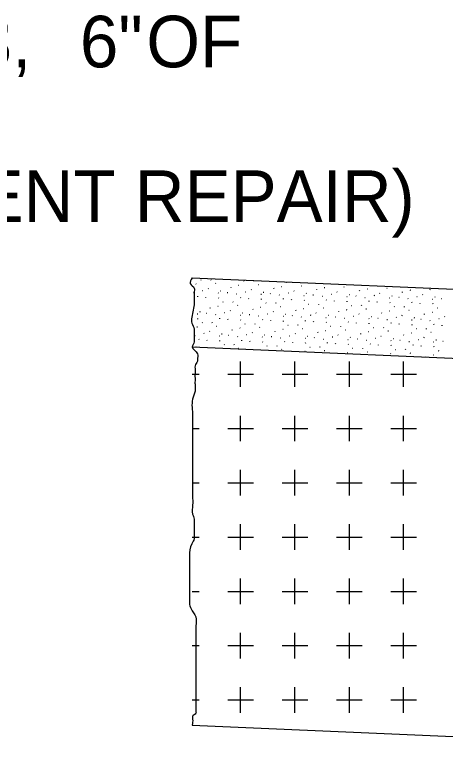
# Model space of a CAD drawing. Extents: x 0 to 34, y 0 to 22.
# Drawn here: x 20.152 to 21.318, y 3.808 to 5.839 of the extents above; entities that cross this region are included whole.
import ezdxf

# ---------------------------------------------------------------- set-up
doc = ezdxf.new("R2010")
doc.units = 0
doc.layers.add('TX_P_1', color=7, linetype='Continuous')

msp = doc.modelspace()

# ---------------------------------------------------------------- linework, layer by layer
at = {"layer": 'TX_P_1'}
for p, q in [((20.6558, 5.1199), (20.6569, 5.1197)), ((20.6839, 5.1187), (20.6833, 5.1201)), ((20.6421, 5.1086), (20.6431, 5.1082)), ((20.6953, 5.1104), (20.6964, 5.1102)), ((20.7383, 5.0987), (20.7378, 5.1002)), ((20.7583, 5.1052), (20.7593, 5.1051)), ((20.7721, 5.1167), (20.7731, 5.1166)), ((20.8003, 5.1154), (20.7996, 5.1169)), ((20.8116, 5.1071), (20.8126, 5.1069)), ((20.8746, 5.1021), (20.8756, 5.1017)), ((20.8883, 5.1134), (20.8893, 5.1132)), ((20.9164, 5.1122), (20.9161, 5.1131)), ((20.9278, 5.1039), (20.9289, 5.1037)), ((20.9908, 5.0987), (20.9919, 5.0986)), ((21.0441, 5.1006), (21.0451, 5.1004)), ((20.6361, 5.0852), (20.6371, 5.0849)), ((20.6606, 5.0907), (20.6616, 5.0906)), ((20.6758, 5.0966), (20.6769, 5.0957)), ((20.7029, 5.0841), (20.7039, 5.0839)), ((20.7091, 5.0899), (20.7103, 5.0896)), ((20.7276, 5.0857), (20.7288, 5.0854)), ((20.7523, 5.0819), (20.7534, 5.0817)), ((20.7768, 5.0876), (20.7779, 5.0874)), ((20.7921, 5.0934), (20.7931, 5.0926)), ((20.8191, 5.0807), (20.8203, 5.0806)), ((20.8254, 5.0866), (20.8264, 5.0864)), ((20.8439, 5.0824), (20.8449, 5.0822)), ((20.8544, 5.0956), (20.8539, 5.0969)), ((20.8686, 5.0786), (20.8696, 5.0784)), ((20.8931, 5.0842), (20.8941, 5.0841)), ((20.9084, 5.0901), (20.9094, 5.0892)), ((20.9416, 5.0834), (20.9428, 5.0831)), ((20.9601, 5.0791), (20.9611, 5.0789)), ((20.9708, 5.0922), (20.9703, 5.0937)), ((21.0093, 5.0811), (21.0104, 5.0809)), ((21.0246, 5.0869), (21.0256, 5.0861)), ((21.0579, 5.0801), (21.0591, 5.0799)), ((21.0871, 5.0891), (21.0866, 5.0904)), ((21.1071, 5.0956), (21.1081, 5.0952)), ((21.1256, 5.0777), (21.1268, 5.0776)), ((21.1409, 5.0836), (21.1419, 5.0827)), ((21.1604, 5.0974), (21.1614, 5.0972)), ((21.2033, 5.0857), (21.2028, 5.0871)), ((21.2233, 5.0922), (21.2244, 5.0921)), ((21.2571, 5.0804), (21.2581, 5.0794)), ((21.2766, 5.0941), (21.2776, 5.0939)), ((20.6479, 5.0739), (20.6473, 5.0754)), ((20.6699, 5.0714), (20.6694, 5.0727)), ((20.7044, 5.0699), (20.7039, 5.0712)), ((20.7154, 5.0602), (20.7166, 5.0599)), ((20.7436, 5.0589), (20.7431, 5.0604)), ((20.7643, 5.0707), (20.7636, 5.0721)), ((20.7861, 5.0681), (20.7856, 5.0694)), ((20.8208, 5.0666), (20.8203, 5.0681)), ((20.8804, 5.0674), (20.8799, 5.0689)), ((20.9024, 5.0649), (20.9018, 5.0662)), ((20.9354, 5.0774), (20.9364, 5.0772)), ((20.9369, 5.0634), (20.9364, 5.0647)), ((20.9849, 5.0754), (20.9859, 5.0751)), ((20.9966, 5.0642), (20.9961, 5.0656)), ((21.0188, 5.0616), (21.0181, 5.0629)), ((21.0516, 5.0742), (21.0528, 5.0741)), ((21.0533, 5.0601), (21.0528, 5.0616)), ((21.0764, 5.0759), (21.0774, 5.0756)), ((21.1011, 5.0721), (21.1021, 5.0719)), ((21.1129, 5.0609), (21.1124, 5.0624)), ((21.1349, 5.0584), (21.1344, 5.0597)), ((21.1679, 5.0709), (21.1689, 5.0707)), ((21.1696, 5.0569), (21.1689, 5.0582)), ((21.1743, 5.0767), (21.1753, 5.0766)), ((21.1926, 5.0726), (21.1936, 5.0724)), ((21.2173, 5.0689), (21.2184, 5.0686)), ((21.2291, 5.0577), (21.2286, 5.0591)), ((21.2419, 5.0744), (21.2429, 5.0742)), ((21.2841, 5.0677), (21.2853, 5.0676)), ((21.2904, 5.0736), (21.2914, 5.0732)), ((21.3089, 5.0694), (21.3099, 5.0691)), ((20.6388, 5.0539), (20.6398, 5.0537)), ((20.6818, 5.0422), (20.6813, 5.0437)), ((20.7018, 5.0487), (20.7029, 5.0486)), ((20.7551, 5.0507), (20.7561, 5.0504)), ((20.7979, 5.0391), (20.7974, 5.0404)), ((20.8181, 5.0456), (20.8191, 5.0454)), ((20.8318, 5.0569), (20.8328, 5.0567)), ((20.8599, 5.0557), (20.8594, 5.0571)), ((20.8713, 5.0474), (20.8724, 5.0472)), ((20.9143, 5.0357), (20.9138, 5.0371)), ((20.9343, 5.0422), (20.9354, 5.0421)), ((20.9481, 5.0537), (20.9491, 5.0534)), ((20.9761, 5.0524), (20.9756, 5.0539)), ((20.9876, 5.0442), (20.9886, 5.0439)), ((21.0506, 5.0389), (21.0518, 5.0387)), ((21.0643, 5.0504), (21.0654, 5.0502)), ((21.0924, 5.0492), (21.0919, 5.0506)), ((21.1038, 5.0409), (21.1049, 5.0406)), ((21.1806, 5.0472), (21.1816, 5.0469)), ((21.2088, 5.0459), (21.2081, 5.0474)), ((21.2201, 5.0376), (21.2211, 5.0374)), ((21.2511, 5.0551), (21.2506, 5.0564)), ((21.2858, 5.0536), (21.2853, 5.0551)), ((21.2968, 5.0439), (21.2978, 5.0437)), ((20.6463, 5.0276), (20.6474, 5.0274)), ((20.6526, 5.0334), (20.6538, 5.0331)), ((20.6711, 5.0291), (20.6721, 5.0289)), ((20.6959, 5.0254), (20.6969, 5.0252)), ((20.7203, 5.0311), (20.7214, 5.0307)), ((20.7356, 5.0367), (20.7366, 5.0359)), ((20.7626, 5.0242), (20.7638, 5.0241)), ((20.7689, 5.0301), (20.7699, 5.0299)), ((20.7873, 5.0259), (20.7884, 5.0257)), ((20.8121, 5.0221), (20.8131, 5.0219)), ((20.8366, 5.0277), (20.8378, 5.0276)), ((20.8518, 5.0336), (20.8529, 5.0327)), ((20.8789, 5.0211), (20.8799, 5.0209)), ((20.8853, 5.0269), (20.8863, 5.0266)), ((20.9036, 5.0226), (20.9046, 5.0224)), ((20.9283, 5.0189), (20.9294, 5.0187)), ((20.9529, 5.0246), (20.9539, 5.0242)), ((20.9681, 5.0302), (20.9691, 5.0294)), ((20.9951, 5.0177), (20.9963, 5.0176)), ((21.0014, 5.0236), (21.0024, 5.0234)), ((21.0199, 5.0194), (21.0209, 5.0192)), ((21.0306, 5.0326), (21.0299, 5.0339)), ((21.0691, 5.0212), (21.0701, 5.0211)), ((21.0843, 5.0271), (21.0854, 5.0262)), ((21.1176, 5.0204), (21.1188, 5.0201)), ((21.1468, 5.0292), (21.1463, 5.0306)), ((21.1669, 5.0357), (21.1679, 5.0356)), ((21.1854, 5.0181), (21.1864, 5.0177)), ((21.2006, 5.0237), (21.2018, 5.0229)), ((21.2339, 5.0171), (21.2351, 5.0169)), ((21.2629, 5.0261), (21.2624, 5.0274)), ((21.2831, 5.0324), (21.2841, 5.0322)), ((21.3169, 5.0206), (21.3179, 5.0197)), ((20.6479, 5.0134), (20.6474, 5.0147)), ((20.6591, 5.0036), (20.6601, 5.0034)), ((20.6871, 5.0024), (20.6866, 5.0037)), ((20.7076, 5.0142), (20.7071, 5.0156)), ((20.7298, 5.0116), (20.7291, 5.0131)), ((20.7643, 5.0102), (20.7638, 5.0116)), ((20.7753, 5.0004), (20.7764, 5.0002)), ((20.8034, 4.9992), (20.8029, 5.0006)), ((20.8239, 5.0111), (20.8234, 5.0124)), ((20.8459, 5.0084), (20.8454, 5.0097)), ((20.8804, 5.0069), (20.8799, 5.0082)), ((20.8916, 4.9971), (20.8926, 4.9969)), ((20.9198, 4.9959), (20.9191, 4.9972)), ((20.9401, 5.0077), (20.9396, 5.0091)), ((20.9621, 5.0051), (20.9616, 5.0064)), ((20.9968, 5.0036), (20.9963, 5.0049)), ((21.0446, 5.0156), (21.0456, 5.0154)), ((21.0564, 5.0044), (21.0559, 5.0057)), ((21.0784, 5.0017), (21.0779, 5.0032)), ((21.1114, 5.0146), (21.1124, 5.0142)), ((21.1129, 5.0004), (21.1124, 5.0017)), ((21.1361, 5.0161), (21.1373, 5.0159)), ((21.1609, 5.0124), (21.1619, 5.0122)), ((21.1728, 5.0012), (21.1721, 5.0026)), ((21.1948, 4.9986), (21.1941, 4.9999)), ((21.2276, 5.0112), (21.2288, 5.0111)), ((21.2293, 4.9971), (21.2288, 4.9984)), ((21.2524, 5.0129), (21.2534, 5.0127)), ((21.2771, 5.0091), (21.2783, 5.0089)), ((21.2889, 4.9979), (21.2884, 4.9992)), ((21.3016, 5.0147), (21.3026, 5.0146)), ((21.3109, 4.9952), (21.3104, 4.9967)), ((20.6453, 4.9922), (20.6464, 4.9921)), ((20.6791, 4.9804), (20.6801, 4.9796)), ((20.6986, 4.9942), (20.6996, 4.9939)), ((20.7414, 4.9826), (20.7409, 4.9839)), ((20.7616, 4.9891), (20.7628, 4.9887)), ((20.7953, 4.9771), (20.7964, 4.9762)), ((20.8148, 4.9909), (20.8159, 4.9907)), ((20.8578, 4.9792), (20.8573, 4.9807)), ((20.8779, 4.9857), (20.8789, 4.9856)), ((20.9311, 4.9876), (20.9321, 4.9874)), ((20.9739, 4.9761), (20.9734, 4.9774)), ((20.9941, 4.9826), (20.9951, 4.9822)), ((21.0078, 4.9939), (21.0088, 4.9937)), ((21.0359, 4.9927), (21.0354, 4.9941)), ((21.0473, 4.9844), (21.0483, 4.9842)), ((21.1103, 4.9792), (21.1114, 4.9791)), ((21.1241, 4.9906), (21.1251, 4.9904)), ((21.1521, 4.9894), (21.1516, 4.9907)), ((21.1636, 4.9811), (21.1646, 4.9809)), ((21.2266, 4.9761), (21.2276, 4.9757)), ((21.2403, 4.9874), (21.2414, 4.9872)), ((21.2684, 4.9862), (21.2679, 4.9876)), ((21.2798, 4.9779), (21.2809, 4.9777)), ((20.6393, 4.9689), (20.6404, 4.9686)), ((20.6511, 4.9577), (20.6506, 4.9591)), ((20.6639, 4.9746), (20.6649, 4.9744)), ((20.6731, 4.9551), (20.6726, 4.9564)), ((20.7061, 4.9677), (20.7073, 4.9676)), ((20.7124, 4.9736), (20.7134, 4.9734)), ((20.7309, 4.9694), (20.7319, 4.9691)), ((20.7556, 4.9656), (20.7566, 4.9654)), ((20.7674, 4.9544), (20.7669, 4.9559)), ((20.7801, 4.9712), (20.7811, 4.9711)), ((20.8224, 4.9646), (20.8234, 4.9642)), ((20.8286, 4.9702), (20.8298, 4.9701)), ((20.8471, 4.9661), (20.8483, 4.9659)), ((20.8719, 4.9624), (20.8729, 4.9621)), ((20.8963, 4.9681), (20.8974, 4.9677)), ((20.9116, 4.9739), (20.9128, 4.9731)), ((20.9386, 4.9612), (20.9396, 4.9611)), ((20.9449, 4.9671), (20.9461, 4.9669)), ((20.9634, 4.9629), (20.9644, 4.9626)), ((20.9881, 4.9591), (20.9891, 4.9589)), ((21.0126, 4.9647), (21.0136, 4.9646)), ((21.0279, 4.9706), (21.0289, 4.9697)), ((21.0549, 4.9581), (21.0559, 4.9577)), ((21.0613, 4.9637), (21.0623, 4.9636)), ((21.0796, 4.9596), (21.0806, 4.9594)), ((21.0903, 4.9727), (21.0898, 4.9742)), ((21.1044, 4.9559), (21.1054, 4.9556)), ((21.1289, 4.9616), (21.1299, 4.9612)), ((21.1441, 4.9672), (21.1451, 4.9664)), ((21.1774, 4.9606), (21.1784, 4.9604)), ((21.1959, 4.9564), (21.1969, 4.9561)), ((21.2066, 4.9694), (21.2061, 4.9709)), ((21.2451, 4.9582), (21.2463, 4.9581)), ((21.2603, 4.9641), (21.2614, 4.9632)), ((21.2938, 4.9572), (21.2948, 4.9571)), ((20.6421, 4.9377), (20.6431, 4.9376)), ((20.7078, 4.9536), (20.7073, 4.9551)), ((20.7188, 4.9439), (20.7198, 4.9437)), ((20.7469, 4.9427), (20.7464, 4.9441)), ((20.7894, 4.9519), (20.7889, 4.9532)), ((20.8239, 4.9504), (20.8234, 4.9517)), ((20.8351, 4.9407), (20.8361, 4.9404)), ((20.8631, 4.9394), (20.8626, 4.9409)), ((20.8838, 4.9512), (20.8831, 4.9526)), ((20.9056, 4.9486), (20.9051, 4.9499)), ((20.9403, 4.9471), (20.9398, 4.9486)), ((20.9513, 4.9374), (20.9524, 4.9372)), ((20.9794, 4.9362), (20.9789, 4.9376)), ((20.9999, 4.9479), (20.9994, 4.9494)), ((21.0219, 4.9454), (21.0214, 4.9467)), ((21.0566, 4.9439), (21.0559, 4.9452)), ((21.1161, 4.9447), (21.1156, 4.9461)), ((21.1383, 4.9421), (21.1376, 4.9434)), ((21.1711, 4.9547), (21.1723, 4.9546)), ((21.1728, 4.9406), (21.1723, 4.9421)), ((21.2206, 4.9526), (21.2216, 4.9524)), ((21.2324, 4.9414), (21.2319, 4.9429)), ((21.2544, 4.9389), (21.2539, 4.9402)), ((21.2874, 4.9516), (21.2884, 4.9512)), ((21.2889, 4.9374), (21.2884, 4.9387)), ((21.3121, 4.9531), (21.3133, 4.9529)), ((20.7583, 4.9344), (20.7593, 4.9342)), ((20.8746, 4.9311), (20.8756, 4.9309)), ((20.9376, 4.9259), (20.9386, 4.9257)), ((20.9908, 4.9279), (20.9919, 4.9276)), ((21.0539, 4.9227), (21.0549, 4.9226)), ((21.0676, 4.9341), (21.0686, 4.9339)), ((21.0958, 4.9329), (21.0953, 4.9342)), ((21.1071, 4.9246), (21.1081, 4.9244)), ((21.1701, 4.9194), (21.1713, 4.9192)), ((21.1838, 4.9309), (21.1849, 4.9306)), ((21.2119, 4.9296), (21.2114, 4.9311)), ((21.2233, 4.9214), (21.2244, 4.9211)), ((21.2864, 4.9162), (21.2874, 4.9161)), ((21.3001, 4.9276), (21.3011, 4.9274)), ((20.7639, 4.8289), (20.7639, 4.8984)), ((20.9113, 4.8637), (20.9113, 4.8984)), ((21.0588, 4.8289), (21.0588, 4.8984)), ((21.2061, 4.8637), (21.2061, 4.8984)), ((21.2661, 4.9101), (21.2658, 4.9111)), ((20.6324, 4.8637), (20.6511, 4.8637)), ((20.7291, 4.8637), (20.7986, 4.8637)), ((20.8766, 4.8637), (20.9113, 4.8637)), ((20.9113, 4.8289), (20.9113, 4.8637)), ((20.9113, 4.8637), (20.9461, 4.8637)), ((21.0239, 4.8637), (21.0934, 4.8637)), ((21.1714, 4.8637), (21.2061, 4.8637)), ((21.2061, 4.8289), (21.2061, 4.8637)), ((21.2061, 4.8637), (21.2409, 4.8637)), ((20.7639, 4.7162), (20.7639, 4.7509)), ((20.9113, 4.6814), (20.9113, 4.7509)), ((21.0588, 4.7162), (21.0588, 4.7509)), ((21.2061, 4.6814), (21.2061, 4.7509)), ((20.6324, 4.7162), (20.6511, 4.7162)), ((20.7291, 4.7162), (20.7639, 4.7162)), ((20.7639, 4.6814), (20.7639, 4.7162)), ((20.7639, 4.7162), (20.7986, 4.7162)), ((20.8766, 4.7162), (20.9461, 4.7162)), ((21.0239, 4.7162), (21.0588, 4.7162)), ((21.0588, 4.6814), (21.0588, 4.7162)), ((21.0588, 4.7162), (21.0934, 4.7162)), ((21.1714, 4.7162), (21.2409, 4.7162)), ((20.7639, 4.5341), (20.7639, 4.6036)), ((20.9113, 4.5687), (20.9113, 4.6036)), ((21.0588, 4.5341), (21.0588, 4.6036)), ((21.2061, 4.5687), (21.2061, 4.6036)), ((20.6324, 4.5687), (20.6511, 4.5687)), ((20.7291, 4.5687), (20.7986, 4.5687)), ((20.8766, 4.5687), (20.9113, 4.5687)), ((20.9113, 4.5341), (20.9113, 4.5687)), ((20.9113, 4.5687), (20.9461, 4.5687)), ((21.0239, 4.5687), (21.0934, 4.5687)), ((21.1714, 4.5687), (21.2061, 4.5687)), ((21.2061, 4.5341), (21.2061, 4.5687)), ((21.2061, 4.5687), (21.2409, 4.5687)), ((20.7639, 4.4214), (20.7639, 4.4561)), ((20.9113, 4.3866), (20.9113, 4.4561)), ((21.0588, 4.4214), (21.0588, 4.4561)), ((21.2061, 4.3866), (21.2061, 4.4561)), ((20.6324, 4.4214), (20.6511, 4.4214)), ((20.7291, 4.4214), (20.7639, 4.4214)), ((20.7639, 4.3866), (20.7639, 4.4214)), ((20.7639, 4.4214), (20.7986, 4.4214)), ((20.8766, 4.4214), (20.9461, 4.4214)), ((21.0239, 4.4214), (21.0588, 4.4214)), ((21.0588, 4.3866), (21.0588, 4.4214)), ((21.0588, 4.4214), (21.0934, 4.4214)), ((21.1714, 4.4214), (21.2409, 4.4214)), ((20.7639, 4.2392), (20.7639, 4.3087)), ((20.9113, 4.2739), (20.9113, 4.3087)), ((21.0588, 4.2392), (21.0588, 4.3087)), ((21.2061, 4.2739), (21.2061, 4.3087)), ((20.6324, 4.2739), (20.6511, 4.2739)), ((20.7291, 4.2739), (20.7986, 4.2739)), ((20.8766, 4.2739), (20.9113, 4.2739)), ((20.9113, 4.2392), (20.9113, 4.2739)), ((20.9113, 4.2739), (20.9461, 4.2739)), ((21.0239, 4.2739), (21.0934, 4.2739)), ((21.1714, 4.2739), (21.2061, 4.2739)), ((21.2061, 4.2392), (21.2061, 4.2739)), ((21.2061, 4.2739), (21.2409, 4.2739)), ((20.7639, 4.1266), (20.7639, 4.1614)), ((20.9113, 4.0919), (20.9113, 4.1614)), ((21.0588, 4.1266), (21.0588, 4.1614)), ((21.2061, 4.0919), (21.2061, 4.1614)), ((20.6324, 4.1266), (20.6511, 4.1266)), ((20.7291, 4.1266), (20.7639, 4.1266)), ((20.7639, 4.0919), (20.7639, 4.1266)), ((20.7639, 4.1266), (20.7986, 4.1266)), ((20.8766, 4.1266), (20.9461, 4.1266)), ((21.0239, 4.1266), (21.0588, 4.1266)), ((21.0588, 4.0919), (21.0588, 4.1266)), ((21.0588, 4.1266), (21.0934, 4.1266)), ((21.1714, 4.1266), (21.2409, 4.1266)), ((20.7639, 3.9444), (20.7639, 4.0139)), ((20.9113, 3.9792), (20.9113, 4.0139)), ((21.0588, 3.9444), (21.0588, 4.0139)), ((21.2061, 3.9792), (21.2061, 4.0139)), ((20.6324, 3.9792), (20.6511, 3.9792)), ((20.7291, 3.9792), (20.7986, 3.9792)), ((20.8766, 3.9792), (20.9113, 3.9792)), ((20.9113, 3.9444), (20.9113, 3.9792)), ((20.9113, 3.9792), (20.9461, 3.9792)), ((21.0239, 3.9792), (21.0934, 3.9792)), ((21.1714, 3.9792), (21.2061, 3.9792)), ((21.2061, 3.9444), (21.2061, 3.9792)), ((21.2061, 3.9792), (21.2409, 3.9792))]:
    msp.add_line(p, q, dxfattribs=at)
for points in [[(20.6324, 5.1254), (21.5936, 5.0837)], [(20.6324, 4.9376), (21.5861, 4.8962)], [(20.6324, 3.9109), (22.9864, 3.8089), (22.9939, 3.8079)]]:
    msp.add_lwpolyline(points, dxfattribs=at)
msp.add_spline([(20.6324, 5.1254), (20.6271, 5.1094), (20.6379, 5.0974), (20.6379, 5.0852), (20.6379, 5.0812), (20.6379, 5.0691), (20.6379, 5.0569), (20.6314, 5.0184), (20.6314, 5.0022), (20.6379, 4.9861), (20.6379, 4.9779), (20.6379, 4.9739), (20.6379, 4.9657), (20.6379, 4.9556), (20.6379, 4.9516), (20.6324, 4.9376), (20.6466, 4.9192), (20.6466, 4.9031), (20.6466, 4.8989), (20.6401, 4.8867), (20.6401, 4.8787), (20.6401, 4.8666), (20.6401, 4.8484), (20.6401, 4.8362), (20.6401, 4.8179), (20.6336, 4.7957), (20.6336, 4.7511), (20.6336, 4.7349), (20.6336, 4.7026), (20.6336, 4.6742), (20.6336, 4.6519), (20.6336, 4.6397), (20.6336, 4.6136), (20.6336, 4.6094), (20.6336, 4.5972), (20.6336, 4.5811), (20.6336, 4.5629), (20.6336, 4.5547), (20.6336, 4.5324), (20.6336, 4.5082), (20.6336, 4.4839), (20.6379, 4.4697), (20.6379, 4.4616), (20.6379, 4.4536), (20.6379, 4.4332), (20.6379, 4.4251), (20.6379, 4.4171), (20.6314, 4.4029), (20.6251, 4.3706), (20.6251, 4.3624), (20.6251, 4.3442), (20.6251, 4.3361), (20.6251, 4.3239), (20.6251, 4.3057), (20.6251, 4.2936), (20.6251, 4.2754), (20.6251, 4.2551), (20.6251, 4.2429), (20.6293, 4.2267), (20.6423, 4.2044), (20.6423, 4.1802), (20.6423, 4.1559), (20.6423, 4.1356), (20.6423, 4.0992), (20.6423, 4.0627), (20.6423, 4.0406), (20.6423, 4.0142), (20.6423, 3.9959), (20.6423, 3.9777), (20.6423, 3.9737), (20.6423, 3.9554), (20.6423, 3.9514), (20.6423, 3.9432), (20.6336, 3.9352), (20.6336, 3.9271), (20.6324, 3.9109)], degree=3, dxfattribs=at)

# ---------------------------------------------------------------- texts
for s, p in [('ITEM 253,      OF', (19.3324, 5.6968)), ('6"', (20.3279, 5.6966)), ('(PAVEMENT REPAIR)', (19.3324, 5.2768))]:
    msp.add_text(s, height=0.14, dxfattribs=at).set_placement(p)

doc.saveas('drawing.dxf')
